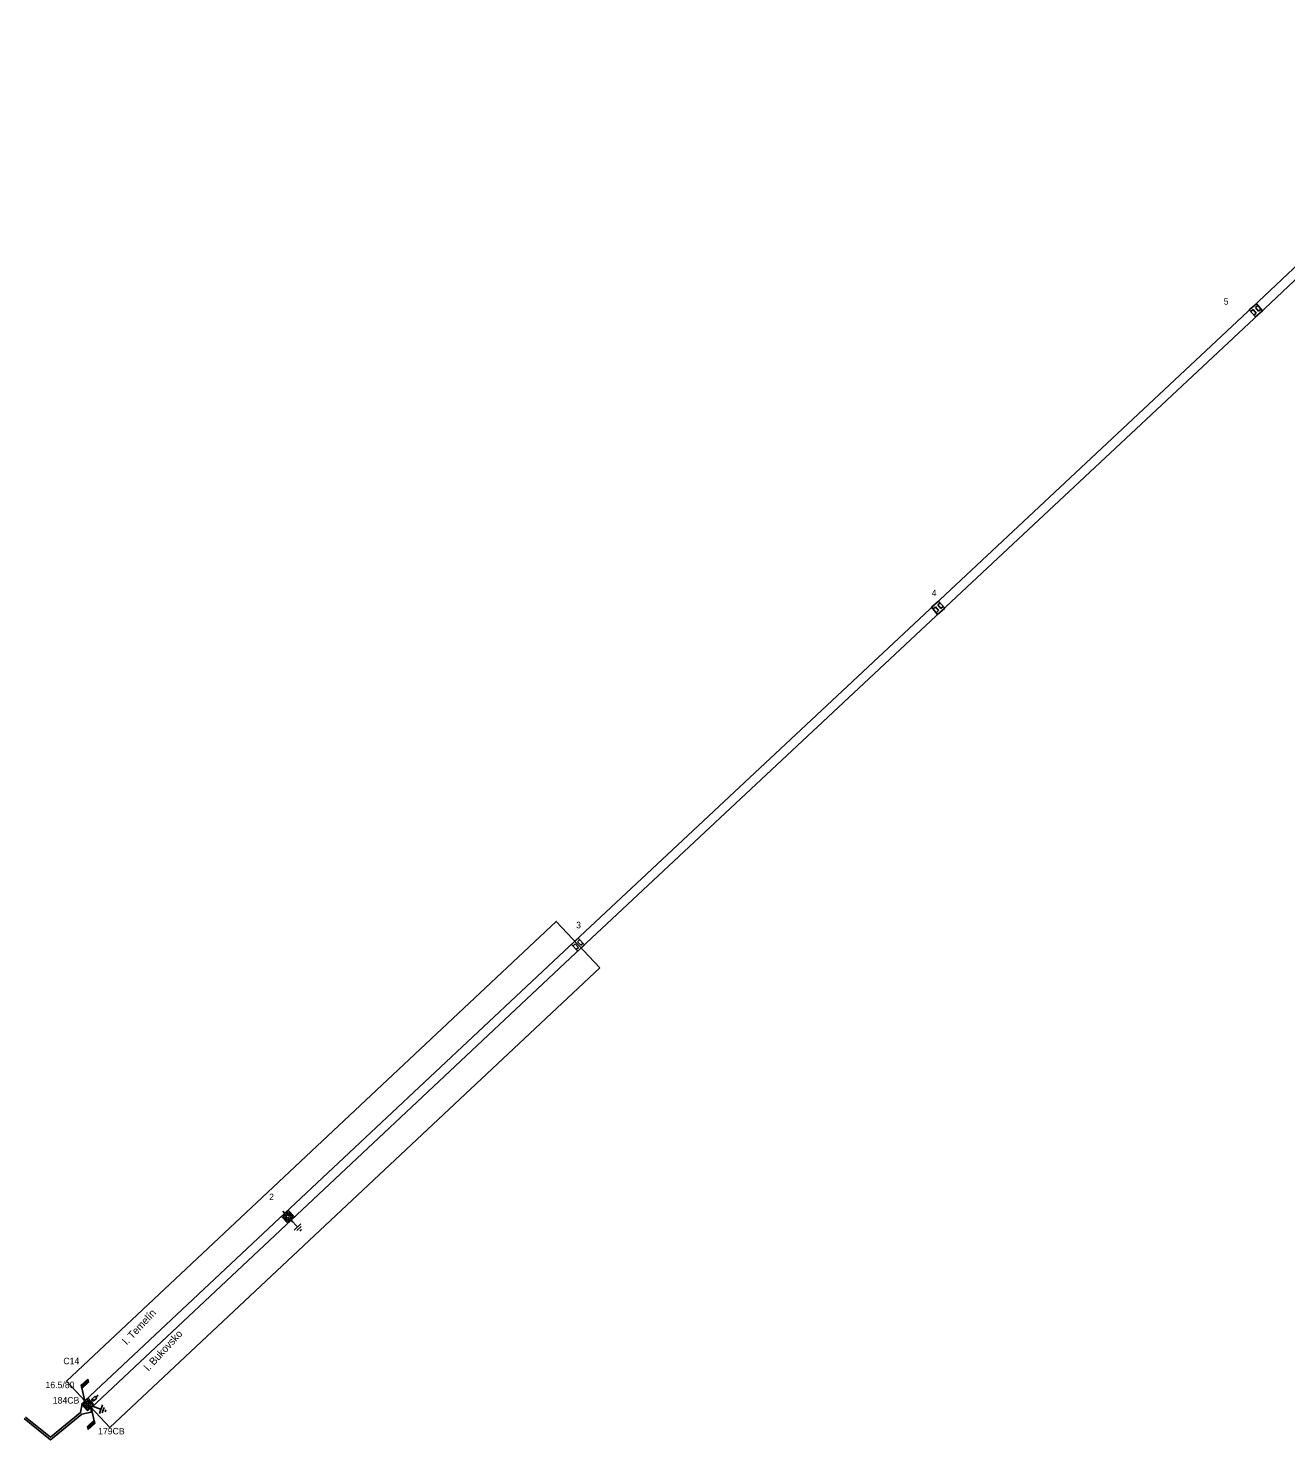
# Model space of a CAD drawing. Extents: x -762500 to -761250, y -1153000 to -1152000.
# Drawn here: x -762223.1 to -761886.4, y -1152648.1 to -1152269.8 of the extents above; entities that cross this region are included whole.
import ezdxf

# ---------------------------------------------------------------- set-up
doc = ezdxf.new("R2010")
doc.units = 0
for name, color, linetype in [('Vrstva 1', 7, 'Continuous'), ('Vrstva 11', 7, 'Continuous'), ('Vrstva 12', 7, 'Continuous'), ('Vrstva 13', 7, 'Continuous'), ('Vrstva 14', 7, 'Continuous'), ('Vrstva 15', 7, 'Continuous'), ('Vrstva 16', 7, 'Continuous'), ('Vrstva 3', 7, 'Continuous'), ('Vrstva 35', 7, 'Continuous'), ('Vrstva 49', 7, 'Continuous'), ('Vrstva 5', 7, 'Continuous')]:
    doc.layers.add(name, color=color, linetype=linetype)

msp = doc.modelspace()

# ---------------------------------------------------------------- linework, layer by layer
at = {"layer": 'Vrstva 1'}
for points in [[(-762207.96, -1152637.64), (-762154.45, -1152587.37), (-762076.76, -1152514.45), (-761980.31, -1152424.19), (-761895.21, -1152344.48), (-761815.94, -1152269.79)], [(-762206.29, -1152639.5), (-762152.73, -1152589.19), (-762075.04, -1152516.27), (-761978.61, -1152426.01), (-761893.49, -1152346.3), (-761816.97, -1152274.17), (-761815.89, -1152271.42)]]:
    msp.add_lwpolyline(points, dxfattribs=at)
at = {"layer": 'Vrstva 11'}
for p, q in [((-762208.945, -1152633.457), (-762208.644, -1152633.176)), ((-762208.932, -1152633.513), (-762207.165, -1152631.866)), ((-762208.919, -1152633.569), (-762207.152, -1152631.922)), ((-762208.906, -1152633.625), (-762207.139, -1152631.978)), ((-762208.893, -1152633.681), (-762207.126, -1152632.034)), ((-762208.879, -1152633.737), (-762207.113, -1152632.091)), ((-762208.866, -1152633.793), (-762207.1, -1152632.147)), ((-762208.853, -1152633.849), (-762207.087, -1152632.203)), ((-762208.84, -1152633.905), (-762207.074, -1152632.259)), ((-762208.826, -1152633.962), (-762207.061, -1152632.316)), ((-762208.813, -1152634.018), (-762207.048, -1152632.372)), ((-762208.8, -1152634.074), (-762207.035, -1152632.428)), ((-762208.787, -1152634.13), (-762207.022, -1152632.484)), ((-762208.774, -1152634.186), (-762207.009, -1152632.541)), ((-762208.76, -1152634.242), (-762206.996, -1152632.597)), ((-762205.49, -1152642.898), (-762207.254, -1152644.543)), ((-762205.476, -1152642.954), (-762207.241, -1152644.6)), ((-762205.463, -1152643.01), (-762207.228, -1152644.656)), ((-762205.45, -1152643.066), (-762207.215, -1152644.712)), ((-762205.437, -1152643.122), (-762207.202, -1152644.768)), ((-762205.424, -1152643.178), (-762207.189, -1152644.825)), ((-762205.41, -1152643.235), (-762207.176, -1152644.881)), ((-762205.397, -1152643.291), (-762207.163, -1152644.937)), ((-762205.384, -1152643.347), (-762207.15, -1152644.993)), ((-762205.371, -1152643.403), (-762207.137, -1152645.05)), ((-762205.357, -1152643.459), (-762207.124, -1152645.106)), ((-762205.344, -1152643.515), (-762207.111, -1152645.162)), ((-762205.331, -1152643.571), (-762207.098, -1152645.218)), ((-762205.318, -1152643.627), (-762207.085, -1152645.275)), ((-762205.305, -1152643.683), (-762205.606, -1152643.964))]:
    msp.add_line(p, q, dxfattribs=at)
for points in [[(-762207.177, -1152631.814), (-762208.946, -1152633.456), (-762208.748, -1152634.294), (-762206.984, -1152632.649)], [(-762207.073, -1152645.326), (-762205.304, -1152643.684), (-762205.502, -1152642.846), (-762207.266, -1152644.491)]]:
    msp.add_lwpolyline(points, close=True, dxfattribs=at)
for points in [[(-762208.946, -1152633.456), (-762207.96, -1152637.64)], [(-762205.304, -1152643.684), (-762206.29, -1152639.5)]]:
    msp.add_lwpolyline(points, dxfattribs=at)
at = {"layer": 'Vrstva 13'}
for points in [[(-761896.112, -1152345.268), (-761894.225, -1152343.628)], [(-761894.472, -1152347.154), (-761896.112, -1152345.268)], [(-761895.084, -1152345.17), (-761895.718, -1152345.721)], [(-761895.085, -1152345.17), (-761894.232, -1152346.151)], [(-761894.232, -1152346.15), (-761894.866, -1152346.701)], [(-761892.586, -1152345.514), (-761894.472, -1152347.154)], [(-761894.466, -1152344.632), (-761893.832, -1152344.081)], [(-761894.466, -1152344.632), (-761893.613, -1152345.613)], [(-761894.225, -1152343.628), (-761892.586, -1152345.514)], [(-761893.613, -1152345.613), (-761892.979, -1152345.061)], [(-761981.222, -1152424.978), (-761979.335, -1152423.338)], [(-761979.582, -1152426.864), (-761981.222, -1152424.978)], [(-761980.194, -1152424.88), (-761980.828, -1152425.431)], [(-761980.195, -1152424.88), (-761979.342, -1152425.861)], [(-761979.342, -1152425.86), (-761979.976, -1152426.411)], [(-761977.696, -1152425.224), (-761979.582, -1152426.864)], [(-761979.576, -1152424.342), (-761978.942, -1152423.791)], [(-761979.576, -1152424.342), (-761978.723, -1152425.323)], [(-761979.335, -1152423.338), (-761977.696, -1152425.224)], [(-761978.723, -1152425.323), (-761978.089, -1152424.772)], [(-762077.665, -1152515.3), (-762075.837, -1152513.595)], [(-762075.96, -1152517.128), (-762077.665, -1152515.3)], [(-762076.641, -1152515.166), (-762077.256, -1152515.738)], [(-762076.642, -1152515.166), (-762075.755, -1152516.117)], [(-762075.755, -1152516.116), (-762076.369, -1152516.689)], [(-762076.042, -1152514.607), (-762075.428, -1152514.034)], [(-762076.042, -1152514.607), (-762075.155, -1152515.557)], [(-762074.132, -1152515.423), (-762075.96, -1152517.128)], [(-762075.837, -1152513.595), (-762074.132, -1152515.423)], [(-762075.156, -1152515.557), (-762074.542, -1152514.984)], [(-762155.323, -1152588.222), (-762153.526, -1152586.547)], [(-762153.647, -1152590.019), (-762155.323, -1152588.222)], [(-762154.424, -1152587.384), (-762154.934, -1152586.837)], [(-762154.875, -1152588.252), (-762153.528, -1152586.995)], [(-762153.619, -1152589.599), (-762154.875, -1152588.252)], [(-762154.455, -1152588.252), (-762153.556, -1152587.415)], [(-762153.616, -1152589.151), (-762154.455, -1152588.252)], [(-762154.047, -1152588.24), (-762153.597, -1152587.821)], [(-762153.628, -1152588.689), (-762154.047, -1152588.24)], [(-762151.85, -1152588.344), (-762153.647, -1152590.019)], [(-762153.179, -1152588.27), (-762153.628, -1152588.689)], [(-762152.271, -1152588.343), (-762153.619, -1152589.599)], [(-762152.718, -1152588.314), (-762153.616, -1152589.151)], [(-762153.597, -1152587.821), (-762153.179, -1152588.27)], [(-762153.556, -1152587.415), (-762152.718, -1152588.314)], [(-762153.528, -1152586.995), (-762152.271, -1152588.343)], [(-762153.526, -1152586.547), (-762151.85, -1152588.344)], [(-762152.748, -1152589.182), (-762152.238, -1152589.729)], [(-762208.923, -1152638.552), (-762207.126, -1152636.877)], [(-762208.024, -1152637.715), (-762208.534, -1152637.167)], [(-762208.475, -1152638.582), (-762207.128, -1152637.325)], [(-762208.055, -1152638.583), (-762207.156, -1152637.745)], [(-762207.156, -1152637.745), (-762206.318, -1152638.644)], [(-762207.128, -1152637.325), (-762205.871, -1152638.673)], [(-762207.126, -1152636.877), (-762205.45, -1152638.674)], [(-762207.247, -1152640.349), (-762208.923, -1152638.552)], [(-762207.219, -1152639.929), (-762208.475, -1152638.582)], [(-762207.217, -1152639.481), (-762208.055, -1152638.583)], [(-762207.647, -1152638.57), (-762207.197, -1152638.151)], [(-762207.228, -1152639.019), (-762207.647, -1152638.57)], [(-762205.45, -1152638.674), (-762207.247, -1152640.349)], [(-762206.779, -1152638.6), (-762207.228, -1152639.019)], [(-762205.871, -1152638.673), (-762207.219, -1152639.929)], [(-762206.318, -1152638.644), (-762207.217, -1152639.481)], [(-762207.197, -1152638.151), (-762206.779, -1152638.6)], [(-762206.349, -1152639.512), (-762205.838, -1152640.059)]]:
    msp.add_lwpolyline(points, dxfattribs=at)
at = {"layer": 'Vrstva 15'}
for points in [[(-762152.737, -1152589.189), (-762151.032, -1152591.018)], [(-762150.118, -1152590.165), (-762151.946, -1152591.87)], [(-762150.048, -1152590.947), (-762151.2, -1152592.022)], [(-762150.18, -1152591.932), (-762150.367, -1152592.106)], [(-762149.985, -1152591.75), (-762150.18, -1152591.932)], [(-762206.017, -1152639.033), (-762203.667, -1152639.888)], [(-762203.24, -1152638.713), (-762204.095, -1152641.063)], [(-762202.822, -1152639.379), (-762203.361, -1152640.859)], [(-762202.493, -1152640.316), (-762202.58, -1152640.556)], [(-762202.402, -1152640.066), (-762202.493, -1152640.316)]]:
    msp.add_lwpolyline(points, dxfattribs=at)
at = {"layer": 'Vrstva 16'}
for points in [[(-762207.194, -1152638.608), (-762205.628, -1152637.199)], [(-762206.203, -1152637.266), (-762205.223, -1152636.384)], [(-762205.762, -1152637.756), (-762206.203, -1152637.266)], [(-762205.628, -1152637.199), (-762205.89, -1152637.276)], [(-762204.782, -1152636.874), (-762205.762, -1152637.756)], [(-762205.628, -1152637.199), (-762205.732, -1152637.451)], [(-762205.223, -1152636.384), (-762204.782, -1152636.874)], [(-762204.999, -1152636.632), (-762204.407, -1152636.099)]]:
    msp.add_lwpolyline(points, dxfattribs=at)
at = {"layer": 'Vrstva 35'}
msp.add_lwpolyline([(-762070.08, -1152521.56), (-762081.72, -1152509.16), (-762212.94, -1152632.35), (-762201.3, -1152644.74)], close=True, dxfattribs=at)
at = {"layer": 'Vrstva 5'}
for points in [[(-762223.85, -1152641.97), (-762217.15, -1152647.35), (-762209.11, -1152640.77), (-762208.68, -1152638.44), (-762207.96, -1152637.64)], [(-762224.2, -1152642.39), (-762217.15, -1152648.06), (-762208.76, -1152641.19), (-762206.33, -1152640.69), (-762206.29, -1152639.5)]]:
    msp.add_lwpolyline(points, dxfattribs=at)

# ---------------------------------------------------------------- texts
at = {"layer": 'Vrstva 12'}
for s, p in [('184CB', (-762216.57, -1152638.36)), ('179CB', (-762204.43, -1152646.62))]:
    msp.add_text(s, height=1.74, dxfattribs=at).set_placement(p)
at = {"layer": 'Vrstva 14'}
for s, p in [('5', (-761902.97, -1152343.88)), ('4', (-761981.16, -1152421.96)), ('3', (-762076.41, -1152510.99)), ('2', (-762158.64, -1152583.85)), ('C14', (-762213.74, -1152627.82))]:
    msp.add_text(s, height=1.74, dxfattribs=at).set_placement(p)
at = {"layer": 'Vrstva 3'}
for s, height, rotation, p in [('l. Temelín', 1.9886, 47.19843, (-762196.67, -1152622.75)), ('l. Bukovsko', 1.98857, 47.25225, (-762190.9, -1152629.78))]:
    msp.add_text(s, height=height, rotation=rotation, dxfattribs=at).set_placement(p)
at = {"layer": 'Vrstva 49'}
msp.add_text('16.5/80', height=1.74, dxfattribs=at).set_placement((-762218.52, -1152634.23))

doc.saveas('drawing.dxf')
